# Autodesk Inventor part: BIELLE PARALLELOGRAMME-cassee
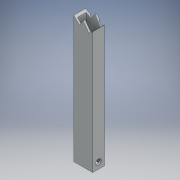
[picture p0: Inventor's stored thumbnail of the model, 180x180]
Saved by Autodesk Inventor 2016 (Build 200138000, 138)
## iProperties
Created: 2013-10
Part Number: BIELLE PARALLELOGRAMME-cassee
Material: solidworks materials|Alliage 1060
Document SubType Name: Modeling
Designer: Bruno
Density: 2.7 g/cm^3
Appearance: 229,234,237
Sending System: SolidWorks 2013
Last Author: christophe
Last Saved: 2014-02-15
Author: Bruno
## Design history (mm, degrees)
feature "Enlèv. mat.-Extru.1"
sketch "Esquisse1"
  geometry: L1 (-1.699, 68.284)-(3.055, 63.657); L2 (3.055, 63.657)-(5, 66.573); L3 (5, 66.573)-(8.064, 62.423); L4 (8.064, 62.423)-(15.226, 68.728); L5 (15.226, 68.728)-(15.226, 123.633); L6 (0, 109)-(0, 0) reference; L7 (15.226, 123.633)-(-17.212, 123.633); L8 (-17.212, 123.633)-(-1.699, 68.284); 1 further point
  constraints: 14 end point, 1 parallel, 1 perpendicular
extrude "Extrusion1" cut sketch "Esquisse1" distance "d0" = 10; taper "d1" = 0 deg
node "Solide1"
